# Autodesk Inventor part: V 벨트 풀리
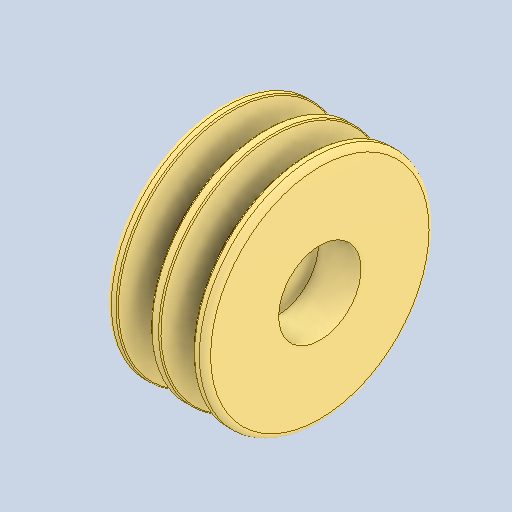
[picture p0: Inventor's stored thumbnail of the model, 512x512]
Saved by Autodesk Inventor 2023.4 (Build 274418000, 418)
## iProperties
Created: 2024-09
Part Number: V 벨트 풀리
Material: 강철, 주조
Document SubType Name: Modeling
Designer: 11
Density: 7.85 g/cm^3
Appearance: 기본값
Author: jhkim
Sending System: Autodesk Inventor 2025
Preprocessor: ST-DEVELOPER v20
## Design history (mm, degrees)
node "V 벨트 풀리1"
node "솔리드2"
node "솔리드1"
